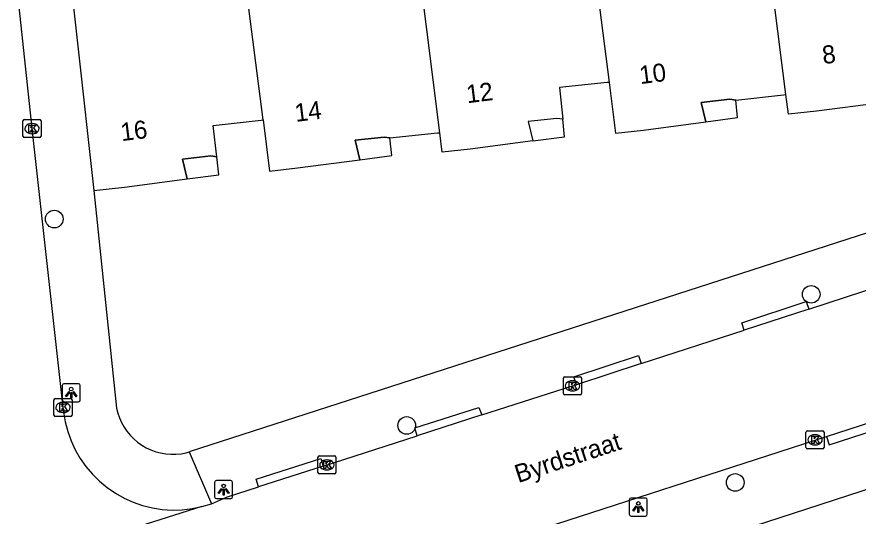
# Model space of a CAD drawing. Extents: x 161253 to 161848, y 384872 to 385383.
# Drawn here: x 161347.65 to 161394.3, y 385046.88 to 385074.55 of the extents above; entities that cross this region are included whole.
import ezdxf

# ---------------------------------------------------------------- set-up
doc = ezdxf.new("R2010")
doc.units = 0
for name, color, linetype in [('IMGEO_Boom', 7, 'Continuous'), ('IMGEO_Kolk', 7, 'Continuous'), ('IMGEO_Lichtpunt', 7, 'Continuous'), ('IMGEO_Openbare_ruimte_label', 7, 'Continuous'), ('IMGEO_Pand', 7, 'Continuous'), ('IMGEO_Pand_nummerreeks', 7, 'Continuous'), ('IMGEO_Pand_overbouw', 7, 'Continuous'), ('IMGEO_Rijbaan_lokaal_open', 7, 'Continuous'), ('IMGEO_Voetpad_open', 7, 'Continuous')]:
    doc.layers.add(name, color=color, linetype=linetype)

msp = doc.modelspace()

# ---------------------------------------------------------------- linework, layer by layer
at = {"layer": 'IMGEO_Boom'}
for centre in [(161349.729, 385063.347), (161391.692, 385059.173), (161369.27, 385051.906), (161387.48, 385048.747)]:
    msp.add_circle(centre, 0.489, dxfattribs=at)
at = {"layer": 'IMGEO_Kolk'}
for p, q in [((161347.995, 385067.931), (161347.995, 385068.783)), ((161348.07, 385068.857), (161348.922, 385068.857)), ((161348.996, 385068.783), (161348.996, 385067.931)), ((161348.483, 385068.637), (161348.508, 385068.637)), ((161348.922, 385067.857), (161348.07, 385067.857)), ((161348.506, 385068.077), (161348.481, 385068.077)), ((161377.96, 385053.676), (161377.96, 385054.528)), ((161378.035, 385054.602), (161378.887, 385054.602)), ((161378.448, 385054.382), (161378.473, 385054.382)), ((161378.961, 385054.528), (161378.961, 385053.676)), ((161378.471, 385053.822), (161378.446, 385053.822)), ((161349.713, 385052.478), (161349.713, 385053.33)), ((161349.788, 385053.404), (161350.64, 385053.404)), ((161350.714, 385053.33), (161350.714, 385052.478)), ((161378.887, 385053.602), (161378.035, 385053.602)), ((161350.201, 385053.184), (161350.226, 385053.184)), ((161350.64, 385052.404), (161349.788, 385052.404)), ((161350.224, 385052.624), (161350.199, 385052.624)), ((161391.404, 385050.683), (161391.404, 385051.535)), ((161391.479, 385051.609), (161392.331, 385051.609)), ((161392.405, 385051.535), (161392.405, 385050.683)), ((161391.892, 385051.389), (161391.917, 385051.389)), ((161392.331, 385050.609), (161391.479, 385050.609)), ((161391.915, 385050.829), (161391.89, 385050.829)), ((161364.347, 385049.295), (161364.347, 385050.147)), ((161364.422, 385050.221), (161365.274, 385050.221)), ((161365.348, 385050.147), (161365.348, 385049.295)), ((161364.835, 385050.001), (161364.86, 385050.001)), ((161365.274, 385049.221), (161364.422, 385049.221)), ((161364.858, 385049.441), (161364.833, 385049.441))]:
    msp.add_line(p, q, dxfattribs=at)
for points in [[(161347.995, 385067.931), (161347.995, 385068.783)], [(161348.07, 385068.857), (161348.922, 385068.857)], [(161348.996, 385068.783), (161348.996, 385067.931)], [(161348.316, 385068.557), (161348.439, 385068.557), (161348.439, 385068.406), (161348.569, 385068.557), (161348.733, 385068.557), (161348.587, 385068.406), (161348.74, 385068.157), (161348.588, 385068.157), (161348.503, 385068.321), (161348.439, 385068.254), (161348.439, 385068.157), (161348.316, 385068.157), (161348.316, 385068.557)], [(161348.922, 385067.857), (161348.07, 385067.857)], [(161377.96, 385053.676), (161377.96, 385054.528)], [(161378.035, 385054.602), (161378.887, 385054.602)], [(161378.281, 385054.302), (161378.404, 385054.302), (161378.404, 385054.151), (161378.534, 385054.302), (161378.698, 385054.302), (161378.552, 385054.151), (161378.705, 385053.902), (161378.553, 385053.902), (161378.468, 385054.066), (161378.404, 385053.999), (161378.404, 385053.902), (161378.281, 385053.902), (161378.281, 385054.302)], [(161378.961, 385054.528), (161378.961, 385053.676)], [(161349.713, 385052.478), (161349.713, 385053.33)], [(161349.788, 385053.404), (161350.64, 385053.404)], [(161350.714, 385053.33), (161350.714, 385052.478)], [(161378.887, 385053.602), (161378.035, 385053.602)], [(161350.034, 385053.104), (161350.157, 385053.104), (161350.157, 385052.953), (161350.287, 385053.104), (161350.451, 385053.104), (161350.305, 385052.953), (161350.458, 385052.704), (161350.306, 385052.704), (161350.221, 385052.868), (161350.157, 385052.801), (161350.157, 385052.704), (161350.034, 385052.704), (161350.034, 385053.104)], [(161350.64, 385052.404), (161349.788, 385052.404)], [(161391.404, 385050.683), (161391.404, 385051.535)], [(161391.479, 385051.609), (161392.331, 385051.609)], [(161392.405, 385051.535), (161392.405, 385050.683)], [(161391.725, 385051.309), (161391.848, 385051.309), (161391.848, 385051.158), (161391.978, 385051.309), (161392.142, 385051.309), (161391.996, 385051.158), (161392.149, 385050.909), (161391.997, 385050.909), (161391.912, 385051.073), (161391.848, 385051.006), (161391.848, 385050.909), (161391.725, 385050.909), (161391.725, 385051.309)], [(161392.331, 385050.609), (161391.479, 385050.609)], [(161364.347, 385049.295), (161364.347, 385050.147)], [(161364.422, 385050.221), (161365.274, 385050.221)], [(161365.348, 385050.147), (161365.348, 385049.295)], [(161364.668, 385049.921), (161364.791, 385049.921), (161364.791, 385049.77), (161364.921, 385049.921), (161365.085, 385049.921), (161364.939, 385049.77), (161365.092, 385049.521), (161364.94, 385049.521), (161364.855, 385049.685), (161364.791, 385049.618), (161364.791, 385049.521), (161364.668, 385049.521), (161364.668, 385049.921)], [(161365.274, 385049.221), (161364.422, 385049.221)]]:
    msp.add_lwpolyline(points, dxfattribs=at)
for centre, start, end in [((161348.072, 385068.781), 91.552, 178.448), ((161348.072, 385068.781), 91.552, 178.448), ((161348.92, 385068.781), 1.552, 88.448), ((161348.92, 385068.781), 1.552, 88.448), ((161348.072, 385067.933), 181.552, 268.448), ((161348.072, 385067.933), 181.552, 268.448), ((161348.92, 385067.933), 271.552, 358.448), ((161348.92, 385067.933), 271.552, 358.448), ((161378.037, 385054.526), 91.552, 178.448), ((161378.037, 385054.526), 91.552, 178.448), ((161378.885, 385054.526), 1.552, 88.448), ((161378.885, 385054.526), 1.552, 88.448), ((161349.79, 385053.328), 91.552, 178.448), ((161349.79, 385053.328), 91.552, 178.448), ((161350.638, 385053.328), 1.552, 88.448), ((161350.638, 385053.328), 1.552, 88.448), ((161378.037, 385053.678), 181.552, 268.448), ((161378.037, 385053.678), 181.552, 268.448), ((161378.885, 385053.678), 271.552, 358.448), ((161378.885, 385053.678), 271.552, 358.448), ((161349.79, 385052.48), 181.552, 268.448), ((161349.79, 385052.48), 181.552, 268.448), ((161350.638, 385052.48), 271.552, 358.448), ((161350.638, 385052.48), 271.552, 358.448), ((161391.481, 385051.533), 91.552, 178.448), ((161391.481, 385051.533), 91.552, 178.448), ((161392.329, 385051.533), 1.552, 88.448), ((161392.329, 385051.533), 1.552, 88.448), ((161391.481, 385050.685), 181.552, 268.448), ((161391.481, 385050.685), 181.552, 268.448), ((161392.329, 385050.685), 271.552, 358.448), ((161392.329, 385050.685), 271.552, 358.448), ((161364.424, 385050.145), 91.552, 178.448), ((161364.424, 385050.145), 91.552, 178.448), ((161365.272, 385050.145), 1.552, 88.448), ((161365.272, 385050.145), 1.552, 88.448), ((161364.424, 385049.297), 181.552, 268.448), ((161364.424, 385049.297), 181.552, 268.448), ((161365.272, 385049.297), 271.552, 358.448), ((161365.272, 385049.297), 271.552, 358.448)]:
    msp.add_arc(centre, 0.0765, start, end, dxfattribs=at)
for centre, major_axis, ratio, start_param, end_param in [((161348.482, 385068.357), (-0.387, 0.002), 0.722429, 4.712389, 7.853982), ((161348.507, 385068.357), (-0.39, 0.002), 0.717154, 1.570796, 4.712389), ((161378.447, 385054.102), (-0.387, 0.002), 0.722429, 4.712389, 7.853982), ((161378.472, 385054.102), (-0.39, 0.002), 0.717154, 1.570796, 4.712389), ((161350.2, 385052.904), (-0.387, 0.002), 0.722429, 4.712389, 7.853982), ((161350.225, 385052.904), (-0.39, 0.002), 0.717154, 1.570796, 4.712389), ((161391.891, 385051.109), (-0.387, 0.002), 0.722429, 4.712389, 7.853982), ((161391.916, 385051.109), (-0.39, 0.002), 0.717154, 1.570796, 4.712389), ((161364.834, 385049.721), (-0.387, 0.002), 0.722429, 4.712389, 7.853982), ((161364.859, 385049.721), (-0.39, 0.002), 0.717154, 1.570796, 4.712389)]:
    msp.add_ellipse(centre, major_axis=major_axis, ratio=ratio, start_param=start_param, end_param=end_param, dxfattribs=at)
at = {"layer": 'IMGEO_Lichtpunt'}
for p, q in [((161350.173, 385054.124), (161350.173, 385053.317)), ((161350.173, 385054.124), (161350.173, 385053.317)), ((161351.075, 385054.219), (161350.267, 385054.219)), ((161351.075, 385054.219), (161350.267, 385054.219)), ((161351.169, 385053.317), (161351.169, 385054.124)), ((161351.169, 385053.317), (161351.169, 385054.124)), ((161350.267, 385053.223), (161351.075, 385053.223)), ((161350.267, 385053.223), (161351.075, 385053.223)), ((161358.621, 385048.755), (161358.621, 385047.948)), ((161358.621, 385048.755), (161358.621, 385047.948)), ((161359.523, 385048.85), (161358.715, 385048.85)), ((161359.523, 385048.85), (161358.715, 385048.85)), ((161359.617, 385047.948), (161359.617, 385048.755)), ((161359.617, 385047.948), (161359.617, 385048.755)), ((161358.715, 385047.854), (161359.523, 385047.854)), ((161358.715, 385047.854), (161359.523, 385047.854)), ((161381.609, 385047.79), (161381.609, 385046.983)), ((161381.609, 385047.79), (161381.609, 385046.983)), ((161382.511, 385047.885), (161381.703, 385047.885)), ((161382.511, 385047.885), (161381.703, 385047.885)), ((161382.605, 385046.983), (161382.605, 385047.79)), ((161382.605, 385046.983), (161382.605, 385047.79)), ((161381.703, 385046.889), (161382.511, 385046.889)), ((161381.703, 385046.889), (161382.511, 385046.889))]:
    msp.add_line(p, q, dxfattribs=at)
for points in [[(161350.547, 385053.788), (161350.586, 385053.76), (161350.398, 385053.498), (161350.36, 385053.525), (161350.547, 385053.788)], [(161350.759, 385053.76), (161350.797, 385053.787), (161350.984, 385053.525), (161350.945, 385053.497), (161350.759, 385053.76)], [(161350.649, 385053.74), (161350.696, 385053.74), (161350.696, 385053.418), (161350.649, 385053.418), (161350.649, 385053.74)], [(161358.995, 385048.419), (161359.034, 385048.391), (161358.846, 385048.129), (161358.808, 385048.156), (161358.995, 385048.419)], [(161359.097, 385048.371), (161359.144, 385048.371), (161359.144, 385048.049), (161359.097, 385048.049), (161359.097, 385048.371)], [(161359.207, 385048.391), (161359.245, 385048.418), (161359.432, 385048.156), (161359.393, 385048.128), (161359.207, 385048.391)], [(161381.983, 385047.454), (161382.022, 385047.426), (161381.834, 385047.164), (161381.796, 385047.191), (161381.983, 385047.454)], [(161382.085, 385047.406), (161382.132, 385047.406), (161382.132, 385047.084), (161382.085, 385047.084), (161382.085, 385047.406)], [(161382.195, 385047.426), (161382.233, 385047.453), (161382.42, 385047.191), (161382.381, 385047.163), (161382.195, 385047.426)]]:
    msp.add_lwpolyline(points, dxfattribs=at)
for centre in [(161350.672, 385053.922), (161359.12, 385048.553), (161382.108, 385047.588)]:
    msp.add_circle(centre, 0.0994, dxfattribs=at)
for centre, start, end in [((161350.267, 385054.124), 90, 180), ((161350.267, 385054.124), 90, 180), ((161351.075, 385054.124), 0, 90), ((161351.075, 385054.124), 0, 90), ((161350.267, 385053.317), 180, 270), ((161350.267, 385053.317), 180, 270), ((161351.075, 385053.317), 270, 0), ((161351.075, 385053.317), 270, 360), ((161358.715, 385048.755), 90, 180), ((161358.715, 385048.755), 90, 180), ((161359.523, 385048.755), 0, 90), ((161359.523, 385048.755), 0, 90), ((161358.715, 385047.948), 180, 270), ((161358.715, 385047.948), 180, 270), ((161359.523, 385047.948), 270, 0), ((161359.523, 385047.948), 270, 360), ((161381.703, 385047.79), 90, 180), ((161381.703, 385047.79), 90, 180), ((161382.511, 385047.79), 0, 90), ((161382.511, 385047.79), 0, 90), ((161381.703, 385046.983), 180, 270), ((161381.703, 385046.983), 180, 270), ((161382.511, 385046.983), 270, 0), ((161382.511, 385046.983), 270, 360)]:
    msp.add_arc(centre, 0.0946, start, end, dxfattribs=at)
at = {"layer": 'IMGEO_Pand'}
for points in [[(161350.119, 385081.284), (161351.915, 385064.931)], [(161390.289, 385070.246), (161389.196, 385078.897)], [(161379.61, 385077.848), (161380.486, 385070.921)], [(161371.106, 385068.129), (161370.015, 385076.798)], [(161361.306, 385068.843), (161360.431, 385075.749)], [(161399.84, 385073.078), (161396.909, 385072.725), (161397.105, 385070.988), (161396.756, 385071.044), (161395.185, 385070.855), (161395.445, 385069.768), (161391.989, 385069.316), (161390.427, 385069.158), (161390.289, 385070.246)], [(161380.486, 385070.921), (161380.373, 385070.909), (161377.734, 385070.637), (161377.919, 385068.889), (161377.597, 385068.925), (161376.01, 385068.756), (161376.26, 385067.675), (161372.789, 385067.223), (161371.242, 385067.048), (161371.106, 385068.129)], [(161380.486, 385070.921), (161380.842, 385068.105), (161382.387, 385068.277), (161385.852, 385068.735), (161385.596, 385069.808), (161387.187, 385069.987), (161387.506, 385069.939), (161390.152, 385070.231), (161390.289, 385070.246)], [(161351.915, 385064.931), (161353.62, 385065.114), (161357.09, 385065.569), (161356.831, 385066.667), (161358.411, 385066.845), (161358.738, 385066.796), (161358.539, 385068.524), (161361.193, 385068.83), (161361.306, 385068.843)], [(161361.306, 385068.843), (161361.665, 385066.004), (161363.208, 385066.176), (161366.667, 385066.632), (161366.42, 385067.711), (161368.015, 385067.887), (161368.329, 385067.844), (161370.967, 385068.115), (161371.106, 385068.129)]]:
    msp.add_lwpolyline(points, dxfattribs=at)
at = {"layer": 'IMGEO_Pand_overbouw'}
for points in [[(161387.506, 385069.939), (161387.187, 385069.987), (161385.596, 385069.808), (161385.852, 385068.735), (161387.613, 385068.968)], [(161377.919, 385068.889), (161377.597, 385068.925), (161376.01, 385068.756), (161376.26, 385067.675), (161378.023, 385067.905)], [(161368.326, 385067.844), (161368.015, 385067.887), (161366.42, 385067.711), (161366.667, 385066.632), (161368.437, 385066.865)], [(161358.738, 385066.796), (161358.411, 385066.845), (161356.831, 385066.667), (161357.09, 385065.569), (161358.853, 385065.8)]]:
    msp.add_lwpolyline(points, close=True, dxfattribs=at)
at = {"layer": 'IMGEO_Rijbaan_lokaal_open'}
for points in [[(161345.081, 385099.589), (161346.704, 385084.797), (161348.495, 385068.357), (161350.213, 385052.904), (161350.244, 385052.658), (161350.335, 385052.113), (161350.474, 385051.578), (161350.661, 385051.057), (161350.893, 385050.555), (161351.17, 385050.076), (161351.488, 385049.624), (161351.845, 385049.202), (161352.238, 385048.813), (161352.665, 385048.461), (161353.121, 385048.149), (161353.603, 385047.878), (161354.108, 385047.652), (161354.63, 385047.472), (161355.167, 385047.339), (161355.714, 385047.255), (161356.265, 385047.219), (161356.818, 385047.234), (161357.367, 385047.297), (161357.909, 385047.41)], [(161391.558, 385058.354), (161397.711, 385060.359)], [(161391.558, 385058.354), (161387.979, 385057.181)], [(161382.273, 385055.346), (161387.979, 385057.181)], [(161382.273, 385055.346), (161378.684, 385054.165)], [(161373.432, 385052.501), (161378.461, 385054.101), (161378.684, 385054.165)], [(161373.432, 385052.501), (161369.85, 385051.335)], [(161392.542, 385051.29), (161396.313, 385052.511)], [(161357.402, 385039.915), (161392.542, 385051.29)], [(161364.64, 385049.653), (161369.85, 385051.335)], [(161364.64, 385049.653), (161361.05, 385048.512)], [(161358.438, 385047.57), (161358.951, 385047.777), (161359.276, 385047.937), (161361.05, 385048.512)], [(161357.909, 385047.41), (161338.624, 385041.3)], [(161357.909, 385047.41), (161358.438, 385047.57)]]:
    msp.add_lwpolyline(points, dxfattribs=at)
at = {"layer": 'IMGEO_Voetpad_open'}
for points in [[(161351.915, 385064.931), (161353.188, 385052.87), (161353.255, 385052.594), (161353.346, 385052.326), (161353.462, 385052.066), (161353.599, 385051.818), (161353.759, 385051.584), (161353.938, 385051.364), (161354.137, 385051.162), (161354.353, 385050.978), (161354.584, 385050.813), (161354.829, 385050.671), (161355.086, 385050.551), (161355.353, 385050.454), (161355.627, 385050.381), (161355.907, 385050.333), (161356.19, 385050.311), (161356.473, 385050.313), (161356.756, 385050.341), (161357.034, 385050.395), (161357.211, 385050.442)], [(161400.77, 385064.501), (161357.211, 385050.442)], [(161387.979, 385057.181), (161387.85, 385057.601), (161391.418, 385058.775), (161391.558, 385058.354)], [(161378.684, 385054.165), (161378.539, 385054.6), (161382.122, 385055.779), (161382.273, 385055.346)], [(161421.765, 385036.754), (161417, 385055.584), (161373.417, 385041.421)], [(161369.85, 385051.335), (161369.713, 385051.767), (161373.275, 385052.908), (161373.432, 385052.501)], [(161392.542, 385051.29), (161392.688, 385050.838), (161396.46, 385052.054), (161396.313, 385052.511)], [(161357.211, 385050.442), (161358.438, 385047.57)], [(161361.05, 385048.512), (161360.921, 385048.925), (161364.502, 385050.072), (161364.64, 385049.653)]]:
    msp.add_lwpolyline(points, dxfattribs=at)

# ---------------------------------------------------------------- texts
at = {"layer": 'IMGEO_Openbare_ruimte_label'}
msp.add_text('Byrdstraat', height=1, rotation=18.1268, dxfattribs=at).set_placement((161375.45, 385048.711))
at = {"layer": 'IMGEO_Pand_nummerreeks'}
for s, rotation, p in [('8', 6.9271, (161392.362, 385071.932)), ('10', 7.1448, (161382.222, 385070.82)), ('12', 7.1047, (161372.63, 385069.761)), ('14', 7.1562, (161363.122, 385068.727)), ('16', 7.0302, (161353.464, 385067.661))]:
    msp.add_text(s, height=1, rotation=rotation, dxfattribs=at).set_placement(p)

doc.saveas('drawing.dxf')
